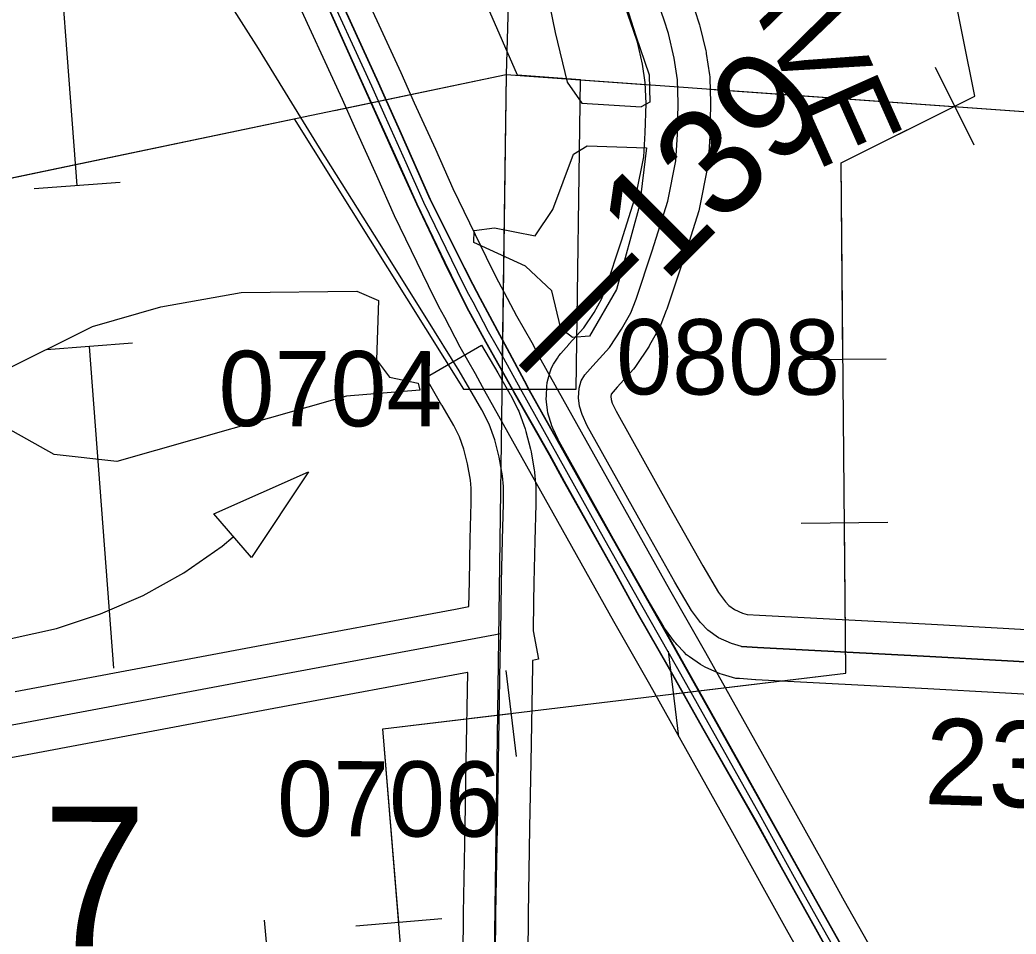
# Model space of a CAD drawing. Extents: x -157.2 to -99.3, y 12.2 to 46.2.
# Drawn here: x -146.27 to -145.344, y 27.455 to 28.305 of the extents above; entities that cross this region are included whole.
import ezdxf

# ---------------------------------------------------------------- set-up
doc = ezdxf.new("R2010")
doc.units = 0
for name, color, linetype in [('tdCoCityStreetMajor', 7, 'Continuous'), ('tdCoCorpBndry', 7, 'Continuous'), ('tdCoDirctArrow', 7, 'Continuous'), ('tdCoDivCarto', 7, 'Continuous'), ('tdCoHydroRiver', 7, 'Continuous'), ('tdCoInt', 7, 'Continuous'), ('tdCoIntCL', 7, 'Continuous'), ('tdCoIntRte', 7, 'Continuous'), ('tdCoPipe', 7, 'Continuous'), ('tdCoSecRdNmbr', 7, 'Continuous'), ('tdCoSecRdTxt', 7, 'Continuous'), ('tdCoSecRteBand', 7, 'Continuous'), ('tdCoSecRteCL', 7, 'Continuous'), ('tdCoSectLine', 7, 'Continuous'), ('tdCoSectLinePart', 7, 'Continuous'), ('tdCoSectNmbr', 7, 'Continuous'), ('tdCoSurfAsphalt', 7, 'Continuous'), ('tdCoSurfGravel', 7, 'Continuous'), ('tdStHwyIntRefPost1', 7, 'Continuous')]:
    doc.layers.add(name, color=color, linetype=linetype)

msp = doc.modelspace()

# ---------------------------------------------------------------- linework, layer by layer
at = {"layer": 'tdCoCityStreetMajor'}
for points in [[(-146.00883, 28.21398), (-146.04824, 28.27806), (-146.09115, 28.34587), (-146.15299, 28.44453)], [(-145.85165, 27.96124), (-145.86156, 27.97818), (-145.89164, 28.02676), (-145.94022, 28.10444), (-145.99152, 28.18582), (-146.00883, 28.21398)]]:
    msp.add_lwpolyline(points, dxfattribs=at)
at = {"layer": 'tdCoCorpBndry'}
msp.add_lwpolyline([(-146.32143, 28.6227), (-146.34546, 28.14362), (-146.015, 28.21263), (-145.85741, 27.96125), (-145.75264, 27.96125), (-145.74875, 28.24895), (-145.80719, 28.25312), (-145.87283, 28.40315)], dxfattribs=at)
at = {"layer": 'tdCoDirctArrow'}
msp.add_lwpolyline([(-146.0898, 27.84551), (-146.00156, 27.88429), (-146.05464, 27.80466)], close=True, dxfattribs=at)
msp.add_lwpolyline([(-146.57124, 27.77848), (-146.53241, 27.75946), (-146.49192, 27.74427), (-146.45016, 27.73305), (-146.40752, 27.72591), (-146.36439, 27.7229), (-146.32116, 27.72405), (-146.27825, 27.72937), (-146.23605, 27.73879), (-146.19495, 27.75222), (-146.15534, 27.76955), (-146.11758, 27.79062), (-146.08202, 27.81522), (-146.07172, 27.82393)], dxfattribs=at)
at = {"layer": 'tdCoDivCarto'}
for points in [[(-145.93633, 28.24586), (-145.96749, 28.31434), (-145.99166, 28.3681), (-146.01547, 28.42149)], [(-145.93633, 28.24586), (-145.96749, 28.31434), (-145.99166, 28.3681), (-146.01547, 28.42149)], [(-145.99482, 28.34239), (-145.95812, 28.26074), (-145.91684, 28.16892)], [(-145.99482, 28.34239), (-145.95812, 28.26074), (-145.91684, 28.16892)], [(-145.85621, 28.07381), (-145.88808, 28.13776), (-145.91644, 28.20164), (-145.93, 28.23197), (-145.93633, 28.24586)], [(-145.85621, 28.07381), (-145.88808, 28.13776), (-145.91644, 28.20164), (-145.93, 28.23197), (-145.93633, 28.24586)], [(-145.91684, 28.16892), (-145.90091, 28.13349), (-145.87502, 28.07924), (-145.86912, 28.06738)], [(-145.91684, 28.16892), (-145.90091, 28.13349), (-145.87502, 28.07924), (-145.86912, 28.06738)], [(-145.84166, 28.04555), (-145.84862, 28.0586), (-145.85621, 28.07381)], [(-145.84166, 28.04555), (-145.84862, 28.0586), (-145.85621, 28.07381)], [(-145.86912, 28.06738), (-145.8543, 28.03756), (-145.83679, 28.00526), (-145.81202, 27.96125)], [(-145.86912, 28.06738), (-145.8543, 28.03756), (-145.83679, 28.00526), (-145.81202, 27.96125)], [(-145.84166, 28.04555), (-145.84166, 28.04555)], [(-145.79843, 27.96458), (-145.84166, 28.04555)], [(-145.79843, 27.96458), (-145.84166, 28.04555)], [(-145.79843, 27.96458), (-145.79843, 27.96458)], [(-145.79665, 27.96125), (-145.79843, 27.96458)], [(-145.79665, 27.96125), (-145.79843, 27.96458)], [(-145.81202, 27.96125), (-145.81139, 27.96013), (-145.77736, 27.9002), (-145.76404, 27.87579), (-145.71867, 27.7949), (-145.69598, 27.75372), (-145.66589, 27.70119), (-145.63507, 27.64595), (-145.58525, 27.5589), (-145.56207, 27.51697), (-145.53001, 27.45951), (-145.50634, 27.4171)], [(-145.81202, 27.96125), (-145.81139, 27.96013), (-145.77736, 27.9002), (-145.76404, 27.87579), (-145.71867, 27.7949), (-145.69598, 27.75372), (-145.66589, 27.70119), (-145.63507, 27.64595), (-145.58525, 27.5589), (-145.56207, 27.51697), (-145.53001, 27.45951), (-145.50634, 27.4171)], [(-145.45529, 27.3538), (-145.53026, 27.48697), (-145.60103, 27.61373), (-145.67107, 27.73876), (-145.73321, 27.84825), (-145.7961, 27.96021), (-145.79661, 27.96117), (-145.79665, 27.96125)], [(-145.45529, 27.3538), (-145.53026, 27.48697), (-145.60103, 27.61373), (-145.67107, 27.73876), (-145.73321, 27.84825), (-145.7961, 27.96021), (-145.79661, 27.96117), (-145.79665, 27.96125)]]:
    msp.add_lwpolyline(points, dxfattribs=at)
at = {"layer": 'tdCoHydroRiver'}
for points in [[(-145.90955, 28.68649), (-145.92006, 28.70263), (-145.91986, 28.70894), (-145.95331, 28.74795), (-145.94064, 28.74911), (-145.87044, 28.67572), (-145.79963, 28.57231), (-145.76268, 28.49528), (-145.69742, 28.28978)], [(-145.90955, 28.68649), (-145.86544, 28.58711), (-145.86585, 28.57449), (-145.84807, 28.53916), (-145.83427, 28.47702), (-145.81489, 28.44157), (-145.80934, 28.41766), (-145.79071, 28.35851), (-145.78456, 28.35356), (-145.77229, 28.29305)], [(-145.77229, 28.29305), (-145.76108, 28.24662), (-145.74746, 28.22708), (-145.69232, 28.22368)], [(-145.69742, 28.28978), (-145.68503, 28.25345), (-145.68428, 28.22815), (-145.69232, 28.22368)], [(-145.74035, 28.01048), (-145.75617, 28.00943), (-145.76695, 28.01768), (-145.77527, 28.0527), (-145.79978, 28.07562), (-145.84798, 28.09775), (-145.84762, 28.10879), (-145.8286, 28.11132), (-145.79096, 28.10376), (-145.77437, 28.12848), (-145.75532, 28.17996), (-145.74244, 28.18744), (-145.68726, 28.18561), (-145.69375, 28.13212), (-145.71526, 28.05387), (-145.74035, 28.01048)], [(-146.17983, 27.89395), (-146.23802, 27.90062), (-146.28917, 27.92916), (-146.3122, 27.94887), (-146.31031, 27.95829), (-146.28919, 27.97654), (-146.20255, 28.01947), (-146.13881, 28.03789), (-146.06418, 28.05121), (-145.95681, 28.05239), (-145.93657, 28.04383), (-145.93838, 27.98861), (-145.92628, 27.97242), (-145.89963, 27.96679), (-145.89826, 27.96043), (-145.96632, 27.95479), (-146.17983, 27.89395)]]:
    msp.add_lwpolyline(points, dxfattribs=at)
at = {"layer": 'tdCoInt'}
for points in [[(-145.40573, 27.31251), (-145.50322, 27.48528), (-145.52352, 27.52184), (-145.55625, 27.58075), (-145.63213, 27.71614), (-145.6656, 27.77479), (-145.78521, 27.9882), (-145.79382, 28.00432), (-145.80785, 28.02913), (-145.8221, 28.05617), (-145.82712, 28.06548), (-145.83629, 28.08378), (-145.86724, 28.14764), (-145.88342, 28.18411), (-145.90306, 28.22728), (-145.91548, 28.25538), (-145.96217, 28.35723), (-145.98314, 28.40488), (-145.99462, 28.43094), (-146.00788, 28.46036), (-146.0346, 28.51881), (-146.05815, 28.5719), (-146.13446, 28.74013)], [(-145.45785, 27.28278), (-145.55557, 27.45597), (-145.60864, 27.55152), (-145.68435, 27.6866), (-145.71782, 27.74525), (-145.83786, 27.95941), (-145.8464, 27.97542), (-145.86052, 28.00037), (-145.87504, 28.02795), (-145.88035, 28.03778), (-145.89011, 28.05725), (-145.92168, 28.12238), (-145.93815, 28.15952), (-145.9578, 28.20272), (-145.9702, 28.23075), (-146.0169, 28.33264), (-146.04943, 28.40653), (-146.06251, 28.43557), (-146.0893, 28.49417), (-146.1129, 28.54734), (-146.19094, 28.71941)]]:
    msp.add_lwpolyline(points, dxfattribs=at)
at = {"layer": 'tdCoIntCL'}
msp.add_lwpolyline([(-145.43179, 27.29765), (-145.52939, 27.47063), (-145.54974, 27.50727), (-145.58245, 27.56614), (-145.65824, 27.70137), (-145.69171, 27.76002), (-145.72568, 27.82062), (-145.80463, 27.96147), (-145.82011, 27.98987), (-145.83418, 28.01475), (-145.84857, 28.04206), (-145.85373, 28.05163), (-145.8632, 28.07052), (-145.89446, 28.13501), (-145.91078, 28.17182), (-145.93043, 28.215), (-145.94284, 28.24306), (-145.98953, 28.34494)], dxfattribs=at)
at = {"layer": 'tdCoIntRte'}
for points in [[(-145.9952, 28.34239), (-145.9585, 28.26074), (-145.91722, 28.16892), (-145.90129, 28.13349), (-145.8754, 28.07924), (-145.8695, 28.06738), (-145.85468, 28.03756), (-145.83717, 28.00526), (-145.8124, 27.96125), (-145.81177, 27.96013), (-145.81061, 27.95808), (-145.77774, 27.9002), (-145.76442, 27.87579), (-145.71905, 27.7949), (-145.69636, 27.75372), (-145.66627, 27.70119), (-145.63545, 27.64595), (-145.58563, 27.5589), (-145.56245, 27.51697), (-145.53039, 27.45951), (-145.50672, 27.4171)], [(-145.9952, 28.34239), (-145.9585, 28.26074), (-145.91722, 28.16892), (-145.90129, 28.13349), (-145.8754, 28.07924), (-145.8695, 28.06738), (-145.85468, 28.03756), (-145.83717, 28.00526), (-145.8124, 27.96125), (-145.81177, 27.96013), (-145.77774, 27.9002), (-145.76442, 27.87579), (-145.71905, 27.7949), (-145.69636, 27.75372), (-145.66627, 27.70119), (-145.63545, 27.64595), (-145.58563, 27.5589), (-145.56245, 27.51697), (-145.53039, 27.45951), (-145.50672, 27.4171)], [(-145.45567, 27.3538), (-145.53063, 27.48697), (-145.60141, 27.61373), (-145.67145, 27.73876), (-145.73359, 27.84825), (-145.79648, 27.96021), (-145.79699, 27.96117), (-145.79703, 27.96125), (-145.79881, 27.96458), (-145.84203, 28.04555), (-145.849, 28.0586), (-145.85658, 28.07381), (-145.88846, 28.13776), (-145.91682, 28.20164), (-145.93038, 28.23197), (-145.9367, 28.24586), (-145.96787, 28.31434)], [(-145.45567, 27.3538), (-145.53063, 27.48697), (-145.60141, 27.61373), (-145.67145, 27.73876), (-145.73359, 27.84825), (-145.79648, 27.96021), (-145.79699, 27.96117), (-145.79703, 27.96125), (-145.79881, 27.96458), (-145.84203, 28.04555), (-145.849, 28.0586), (-145.85658, 28.07381), (-145.88846, 28.13776), (-145.91682, 28.20164), (-145.93038, 28.23197), (-145.9367, 28.24586), (-145.96787, 28.31434)]]:
    msp.add_lwpolyline(points, dxfattribs=at)
at = {"layer": 'tdCoPipe'}
for p, q in [((-145.38278, 28.18828), (-145.41862, 28.26047)), ((-146.17671, 28.15354), (-146.25665, 28.14751)), ((-146.16541, 28.00397), (-146.24535, 27.99793)), ((-145.46444, 27.98923), (-145.54488, 27.9885)), ((-145.46306, 27.8372), (-145.54365, 27.83647)), ((-145.6574, 27.63787), (-145.66697, 27.71774)), ((-145.80835, 27.61978), (-145.81794, 27.6998)), ((-146.03575, 27.38706), (-146.04242, 27.46737)), ((-145.87757, 27.46864), (-145.95774, 27.46203))]:
    msp.add_line(p, q, dxfattribs=at)
for points in [[(-147.12116, 25.03407), (-146.8959, 25.96605), (-146.85327, 26.34559), (-146.82947, 27.003), (-146.63673, 27.37757), (-145.91542, 27.43748), (-145.93257, 27.64548), (-145.50208, 27.69706), (-145.50639, 28.17189), (-145.38212, 28.23359), (-145.52488, 28.94436), (-144.89282, 29.27448), (-144.83425, 30.55895), (-144.65127, 30.94181), (-144.68422, 32.00392)], [(-146.21668, 28.15052), (-146.23926, 28.44967)], [(-145.50473, 27.98886), (-145.50639, 28.17189), (-145.4007, 28.22437)], [(-146.1828, 27.7018), (-146.20538, 28.00095)], [(-145.66219, 27.67787), (-145.50208, 27.69706), (-145.50335, 27.83683)], [(-145.91772, 27.46533), (-145.93257, 27.64548), (-145.81315, 27.65978)]]:
    msp.add_lwpolyline(points, dxfattribs=at)
at = {"layer": 'tdCoSecRteBand'}
for points in [[(-145.21538, 27.67088), (-145.35913, 27.67902), (-145.42566, 27.68271), (-145.58566, 27.6911), (-145.58585, 27.69111), (-145.58605, 27.69112), (-145.60106, 27.6921), (-145.6043, 27.69232), (-145.60742, 27.69322), (-145.61682, 27.69593), (-145.61897, 27.69655), (-145.621, 27.69748), (-145.63284, 27.70291), (-145.63515, 27.70397), (-145.63726, 27.70541), (-145.64737, 27.71231), (-145.65013, 27.7142), (-145.65241, 27.71664), (-145.65906, 27.72379), (-145.66022, 27.72504), (-145.66123, 27.7264), (-145.66962, 27.73775), (-145.67055, 27.73901), (-145.67134, 27.74036), (-145.68688, 27.76675), (-145.68701, 27.76697), (-145.68714, 27.7672), (-145.71797, 27.8217), (-145.71801, 27.82178), (-145.71806, 27.82187), (-145.76862, 27.91262), (-145.76915, 27.91357), (-145.76961, 27.91457), (-145.77454, 27.92517), (-145.77551, 27.92725), (-145.77615, 27.92946), (-145.77837, 27.9371), (-145.77903, 27.93939), (-145.77933, 27.94175), (-145.78031, 27.94964), (-145.78065, 27.95232), (-145.7805, 27.95502), (-145.78001, 27.9639), (-145.77981, 27.9674), (-145.77882, 27.97076), (-145.77684, 27.97742), (-145.77574, 27.98116), (-145.77371, 27.98449), (-145.77025, 27.99017), (-145.76888, 27.99243), (-145.76712, 27.99442), (-145.75972, 28.0028), (-145.75963, 28.0029), (-145.75954, 28.003), (-145.7457, 28.01841), (-145.73617, 28.0327), (-145.72917, 28.0451), (-145.72527, 28.05525), (-145.71052, 28.09926), (-145.69655, 28.14354), (-145.68987, 28.1774), (-145.68854, 28.19952), (-145.68784, 28.22697), (-145.68849, 28.24633), (-145.69101, 28.26335), (-145.69587, 28.28391), (-145.69935, 28.29479), (-145.74714, 28.43252)], [(-145.64232, 28.31342), (-145.63837, 28.30109), (-145.63802, 28.29999), (-145.63775, 28.29886), (-145.63233, 28.27592), (-145.63203, 28.27468), (-145.63185, 28.27341), (-145.62889, 28.25344), (-145.62864, 28.25175), (-145.62858, 28.25005), (-145.62784, 28.2281), (-145.62781, 28.22721), (-145.62783, 28.22632), (-145.62857, 28.19747), (-145.62859, 28.19696), (-145.62862, 28.19644), (-145.6301, 28.17178), (-145.63022, 28.16976), (-145.63061, 28.16777), (-145.63801, 28.13029), (-145.63833, 28.12865), (-145.63883, 28.12707), (-145.65338, 28.08095), (-145.65346, 28.0807), (-145.65354, 28.08045), (-145.66859, 28.03556), (-145.6688, 28.03494), (-145.66903, 28.03433), (-145.67396, 28.0215), (-145.67476, 28.01945), (-145.67584, 28.01753), (-145.68447, 28.00224), (-145.68502, 28.00127), (-145.68563, 28.00034), (-145.69698, 27.98333), (-145.69818, 27.98153), (-145.69962, 27.97992), (-145.71482, 27.963), (-145.72031, 27.95678), (-145.72044, 27.9544), (-145.72009, 27.95155), (-145.71917, 27.94839), (-145.71567, 27.94086), (-145.66569, 27.85115), (-145.63504, 27.79696), (-145.62044, 27.77215), (-145.61399, 27.76344), (-145.61077, 27.75997), (-145.60552, 27.75639), (-145.59803, 27.75296), (-145.5939, 27.75176), (-145.58232, 27.751), (-145.42247, 27.74263), (-145.42242, 27.74263), (-145.42237, 27.74262), (-145.35579, 27.73893), (-145.35578, 27.73892), (-145.35576, 27.73892), (-145.21204, 27.73079)], [(-146.27429, 27.68027), (-146.04497, 27.72317), (-146.04496, 27.72317), (-146.04495, 27.72317), (-145.86496, 27.75671), (-145.8525, 27.75905), (-145.85209, 27.78241), (-145.85209, 27.78243), (-145.85209, 27.78245), (-145.85135, 27.82166), (-145.85135, 27.82181), (-145.85135, 27.82196), (-145.85037, 27.85556), (-145.85037, 27.8692), (-145.85111, 27.87678), (-145.85368, 27.89175), (-145.85723, 27.90552), (-145.8613, 27.91697), (-145.86668, 27.92753), (-145.87753, 27.94608), (-145.87754, 27.9461), (-145.87755, 27.94612), (-145.87756, 27.94613), (-145.89268, 27.97204), (-145.84085, 28.00227), (-145.82574, 27.97636), (-145.81445, 27.95708), (-145.81401, 27.95633), (-145.81362, 27.95555), (-145.80696, 27.94248), (-145.80608, 27.94075), (-145.80543, 27.93892), (-145.80025, 27.92437), (-145.7998, 27.9231), (-145.79946, 27.92179), (-145.79527, 27.90552), (-145.79496, 27.90432), (-145.79475, 27.9031), (-145.79179, 27.88584), (-145.79161, 27.88477), (-145.7915, 27.88368), (-145.79051, 27.87357), (-145.79037, 27.87212), (-145.79037, 27.87066), (-145.79037, 27.85512), (-145.79037, 27.85469), (-145.79039, 27.85426), (-145.79137, 27.82038), (-145.7921, 27.78134), (-145.79241, 27.76356), (-145.79288, 27.73663), (-145.7879, 27.71015), (-145.79336, 27.70913), (-145.79346, 27.70357), (-145.79346, 27.70357), (-145.79506, 27.61417), (-145.79605, 27.55353), (-145.79605, 27.5535), (-145.79605, 27.55347), (-145.79753, 27.47301), (-145.79777, 27.433)], [(-145.85777, 27.43362), (-145.85752, 27.47356), (-145.85752, 27.47374), (-145.85752, 27.47393), (-145.85604, 27.55454), (-145.85505, 27.61517), (-145.85505, 27.6152), (-145.85505, 27.61522), (-145.85358, 27.6978), (-145.85389, 27.69774), (-145.85391, 27.69773), (-145.85394, 27.69773), (-146.03395, 27.66419), (-146.26328, 27.62128), (-146.26332, 27.62128), (-146.26335, 27.62127), (-146.35135, 27.605)]]:
    msp.add_lwpolyline(points, dxfattribs=at)
at = {"layer": 'tdCoSecRteCL'}
for points in [[(-145.21368, 27.70083), (-145.35746, 27.70897), (-145.42404, 27.71267), (-145.58409, 27.72106), (-145.5991, 27.72204), (-145.6085, 27.72475), (-145.62034, 27.73018), (-145.63045, 27.73709), (-145.63711, 27.74424), (-145.64549, 27.75558), (-145.66103, 27.78197), (-145.69185, 27.83647), (-145.74241, 27.92722), (-145.74734, 27.93782), (-145.74956, 27.94547), (-145.75055, 27.95336), (-145.75005, 27.96224), (-145.74808, 27.9689), (-145.74463, 27.97457), (-145.73723, 27.98295), (-145.72194, 27.99997), (-145.7106, 28.01698), (-145.70196, 28.03227), (-145.69703, 28.0451), (-145.68199, 28.08998), (-145.66744, 28.13609), (-145.66004, 28.17358), (-145.65856, 28.19824), (-145.65782, 28.22709), (-145.65856, 28.24904), (-145.66152, 28.26902), (-145.66695, 28.29195), (-145.67089, 28.30428), (-145.71898, 28.44287)], [(-145.82293, 27.73409), (-145.8221, 27.78188), (-145.82136, 27.82109), (-145.82037, 27.85512), (-145.82037, 27.87066), (-145.82136, 27.88077), (-145.82432, 27.89803), (-145.82851, 27.91431), (-145.83369, 27.92886), (-145.84035, 27.94193), (-145.85164, 27.96123), (-145.85165, 27.96124)], [(-147.30705, 27.57774), (-147.28852, 27.57654), (-147.14623, 27.56693), (-146.95881, 27.55435), (-146.85622, 27.54744), (-146.83008, 27.54621), (-146.81898, 27.5472), (-146.78939, 27.55238), (-146.63822, 27.58172), (-146.35684, 27.6345), (-146.2688, 27.65077), (-146.03946, 27.69368), (-145.85943, 27.72722), (-145.82293, 27.73409)], [(-145.82777, 27.43318), (-145.82752, 27.47338), (-145.82604, 27.55402), (-145.82506, 27.61468), (-145.82333, 27.71111), (-145.82293, 27.73409)]]:
    msp.add_lwpolyline(points, dxfattribs=at)
at = {"layer": 'tdCoSectLine'}
for points in [[(-145.79493, 29.05823), (-145.81796, 28.25386)], [(-146.818, 28.04502), (-145.81796, 28.25386)], [(-145.81796, 28.25386), (-145.83185, 27.22776)], [(-145.81796, 28.25386), (-144.7991, 28.18117)]]:
    msp.add_lwpolyline(points, dxfattribs=at)
at = {"layer": 'tdCoSectLinePart'}
for points in [[(-145.80829, 28.59156), (-145.81796, 28.25386)], [(-145.97749, 28.22054), (-145.81796, 28.25386)], [(-145.81796, 28.25386), (-145.82182, 27.96898)], [(-145.81796, 28.25386), (-145.6888, 28.24464)], [(-145.62877, 28.24036), (-145.02721, 28.19744)]]:
    msp.add_lwpolyline(points, dxfattribs=at)
at = {"layer": 'tdCoSurfAsphalt'}
msp.add_line((-145.85164, 27.96123), (-145.85165, 27.96124), dxfattribs=at)
for points in [[(-145.82293, 27.73409), (-145.8221, 27.78188), (-145.82136, 27.82109), (-145.82037, 27.85512), (-145.82037, 27.87066), (-145.82136, 27.88077), (-145.82432, 27.89803), (-145.82851, 27.91431), (-145.83369, 27.92886), (-145.84035, 27.94193), (-145.85164, 27.96123)], [(-145.83154, 27.21868), (-145.83147, 27.22776), (-145.83073, 27.28053), (-145.82974, 27.31678), (-145.829, 27.38016), (-145.82777, 27.43318), (-145.82752, 27.47338), (-145.82604, 27.55402), (-145.82506, 27.61468), (-145.82333, 27.71111), (-145.82293, 27.73409)]]:
    msp.add_lwpolyline(points, dxfattribs=at)
at = {"layer": 'tdCoSurfGravel'}
for points in [[(-145.65782, 28.22709), (-145.65856, 28.24904), (-145.66152, 28.26902), (-145.66695, 28.29195), (-145.67089, 28.30428), (-145.71898, 28.44287), (-145.73402, 28.48159), (-145.76608, 28.56938), (-145.78803, 28.62166), (-145.79617, 28.63523), (-145.80529, 28.64879), (-145.80624, 28.64994)], [(-145.5991, 27.72204), (-145.6085, 27.72475), (-145.62034, 27.73018), (-145.63045, 27.73709), (-145.63711, 27.74424), (-145.64549, 27.75558), (-145.66103, 27.78197), (-145.69185, 27.83647), (-145.74241, 27.92722), (-145.74734, 27.93782), (-145.74956, 27.94547), (-145.75055, 27.95336), (-145.75005, 27.96224), (-145.74808, 27.9689), (-145.74463, 27.97457), (-145.73723, 27.98295), (-145.72194, 27.99997), (-145.7106, 28.01698), (-145.70196, 28.03227), (-145.69703, 28.0451), (-145.68199, 28.08998), (-145.66744, 28.13609), (-145.66004, 28.17358), (-145.65856, 28.19824), (-145.65782, 28.22709)], [(-147.81163, 27.61065), (-147.74746, 27.60786), (-147.60368, 27.59751), (-147.42613, 27.58542), (-147.30705, 27.57774), (-147.28852, 27.57654), (-147.14623, 27.56693), (-146.95881, 27.55435), (-146.85622, 27.54744), (-146.83008, 27.54621), (-146.81898, 27.5472), (-146.78939, 27.55238), (-146.63822, 27.58172), (-146.35684, 27.6345), (-146.2688, 27.65077), (-146.03946, 27.69368), (-145.85943, 27.72722), (-145.82293, 27.73409)], [(-145.5991, 27.72204), (-145.58409, 27.72106), (-145.42404, 27.71267), (-145.35746, 27.70897), (-145.21368, 27.70083), (-145.08348, 27.69393), (-144.94192, 27.68604), (-144.84698, 27.68086), (-144.80516, 27.6781), (-144.76486, 27.67543), (-144.75105, 27.67519), (-144.74192, 27.67716), (-144.73428, 27.68037), (-144.72895, 27.68392)]]:
    msp.add_lwpolyline(points, dxfattribs=at)

# ---------------------------------------------------------------- texts
at = {"layer": 'tdCoSecRdNmbr'}
for s, rotation, p in [('0808', 359.88894, (-145.7157, 27.95646)), ('0704', 359.88846, (-146.0854, 27.927)), ('0706', 359.88868, (-146.03096, 27.54552))]:
    msp.add_text(s, height=0.07, rotation=rotation, dxfattribs=at).set_placement(p)
at = {"layer": 'tdCoSecRdTxt'}
for s, rotation, p in [('BANNER AVE', 294, (-145.80078, 28.79391)), ('235TH ST', 358.09976, (-145.42975, 27.5756))]:
    msp.add_text(s, height=0.08, rotation=rotation, dxfattribs=at).set_placement(p)
at = {"layer": 'tdCoSectNmbr'}
msp.add_text('7', height=0.13, rotation=359.88822, dxfattribs=at).set_placement((-146.24909, 27.44316))
at = {"layer": 'tdStHwyIntRefPost1'}
msp.add_text('‒‒139', height=0.1, rotation=45, dxfattribs=at).set_placement((-145.77659, 27.95383))

doc.saveas('drawing.dxf')
